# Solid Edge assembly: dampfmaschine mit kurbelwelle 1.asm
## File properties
Author: ra-tv
Template: Normal.asm
Last saved by: ra-11
Revision: 15
Application: Solid Edge
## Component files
Grundplatte.par
Kurbenwellenhalter.par
Kurbelwelle.par
Pleuel1.par
Kolben.par
Kurbelwellenplatte 1.par
Kurbelwellenplatte2.par
rper mit zwei Bohrungen.par
Pleuel2.par
Stift 1mm.par
Stift 3mm.par
